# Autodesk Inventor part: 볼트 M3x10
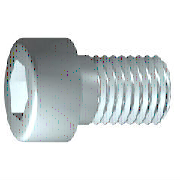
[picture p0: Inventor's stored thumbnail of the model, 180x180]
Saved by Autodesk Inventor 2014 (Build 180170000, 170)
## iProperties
Created: 2012-02
Part Number: 볼트 M3x10
Material: 스테인리스강
Description: 6각 소켓 머리 캡 나사
Document SubType Name: Modeling
Standard: ISO 4762
Designer: mduedu
Standard Revision: Fourth edition 2004-03-01
Standards Organization: ISO
Language: ko-KR
Size Designation: M3 x 10
Categories: <MemberInstance><Categories><Category DisplayName="조임쇠" InternalName="e4da775c-781d-43d5-af7c-5136215cf5a6" Mnemonic="FSTN"><Category DisplayName="볼트" InternalN
Density: 8.08 g/cm^3
Mass: 1.0701 g
Surface Area: 2.01851 cm^2
Volume: 0.132438 cm^3
Appearance: 반광택
IsCustomPart: 0
Author: mduedu
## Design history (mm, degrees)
sketch "스케치1"
  geometry: L1 (-0.867, 0)-(10, 0); L2 (10, 0)-(10, 1.5); L3 (10, 1.5)-(1.25, 1.5); L4 (1.25, 1.5)-(0.943, 1.5); L5 (0.943, 1.5)-(0, 1.5); L6 (0, 1.5)-(0, 2.75); L7 (0, 2.75)-(-3, 2.75); L8 (-3, 2.75)-(-3, 1.443); L9 (-3, 1.443)-(-1.7, 1.443); L10 (-1.7, 1.443)-(-0.867, 0); L11 (-5.6, 0)-(12.6, 0) reference; L12 (0, -0.55)-(0, 3.3) reference; L13 (1.25, 1.5)-(0, 1.5)
  constraints: 22 end point, 6 parallel, 2 collinear, 2 perpendicular, 1 horizontal, 1 point on line
  dimensions: "d1" = 8.75 distance from line of L3.end L2 (= GEL); "d2" = 0.30683 distance of L4.end L3.end (computed from GAL); "d3" = 3 distance between parallel lines of L8 L6 (= KOH); "d4" = 1.3 distance of L8.end L9.end (= INTI); "d5" = 60 deg angle of L10 L1; "d6" = 3 diameter of L3 L1 (= GD); "d7" = 3 diameter of L5 L1 (= BDM); "d8" = 2.88675 diameter of L9 L1 (= 1.1547 x SW); "d9" = 5.5 diameter of L7 L1 (= KOD); "d26" = 10 distance between parallel lines of L12 L2 (= NLG)
revolve "본체" sketch "스케치1" stored, may be unused: angle "d10" = 90 deg
sketch "스케치2"
  geometry: L1 (0, -3.85)-(0, 3.85) reference; L2 (-3.85, 0)-(3.85, 0) reference; L3 (1.443, 0)-(0.722, -1.25); L4 (0.722, -1.25)-(-0.722, -1.25); L5 (-0.722, -1.25)-(-1.443, 0); L6 (-1.443, 0)-(-0.722, 1.25); L7 (-0.722, 1.25)-(0.722, 1.25); L8 (0.722, 1.25)-(1.443, 0); 2 further points
  constraints: 12 end point, 1 coincident, 1 horizontal alignment, 1 point on line, 12 other
extrude "슬롯" join sketch "스케치2" stored distance "d11" = 10; taper "d12" = 0 deg
workplane "Work Plane1"
fillet "Fillet2" dims "d30" = 0.1 (= R)
body "Solid1"
fillet "모깎기1" dims "d17" = 0.3 (= RR)
feature "스레드" dims "d13" = 8.75 (= GEL), "d14" = 0
chamfer "모따기1" distance "d15" = 0.30673 (= -0.5 x SPD + 0.5 x GD); stored, may be unused: second distance "d16" = 0.30673 (= GUL), angle "d27" = 45 deg
other parameters: "GD" = 3 [user parameter; used in 2 equation terms], "NLG" = 10 [user parameter; used in 1 equation term], "GEL" = 8.75 [user parameter; used in 2 equation terms], "KOD" = 5.5 [user parameter; used in 1 equation term], "KOH" = 3 [user parameter; used in 1 equation term], "INTI" = 1.3 [user parameter; used in 1 equation term], "GAL" = 0.30673 (= 0.61345 x PTC) [user parameter; used in 1 equation term], "GUL" = 0.30673 (= 0.61345 x PTC) [user parameter; used in 1 equation term], "BDM" = 3 (= NND) [user parameter; used in 1 equation term], "SW" = 2.5 [user parameter; used in 2 equation terms], "RR" = 0.3 [user parameter; used in 1 equation term], "SPD" = 2.38655 (= NND - 1.2269 x PTC) [user parameter; used in 1 equation term], "d19" = 0, "d28" = 0, "d29" = 0, "R" = 0.1 [user parameter; used in 1 equation term], "TOA" = 30 deg [user parameter], "GD1" = 2.38655 (= THREADDIA - 1.2269 x PTC) [user parameter], "THREADDIA" = 3 [user parameter; used in 1 equation term], "FAWI" = 45 deg [user parameter], "PTC" = 0.5 [user parameter; used in 5 equation terms], "NND" = 3 [user parameter; used in 2 equation terms], "E0" = 2.8875 (= 1.155 x SW) [user parameter]
